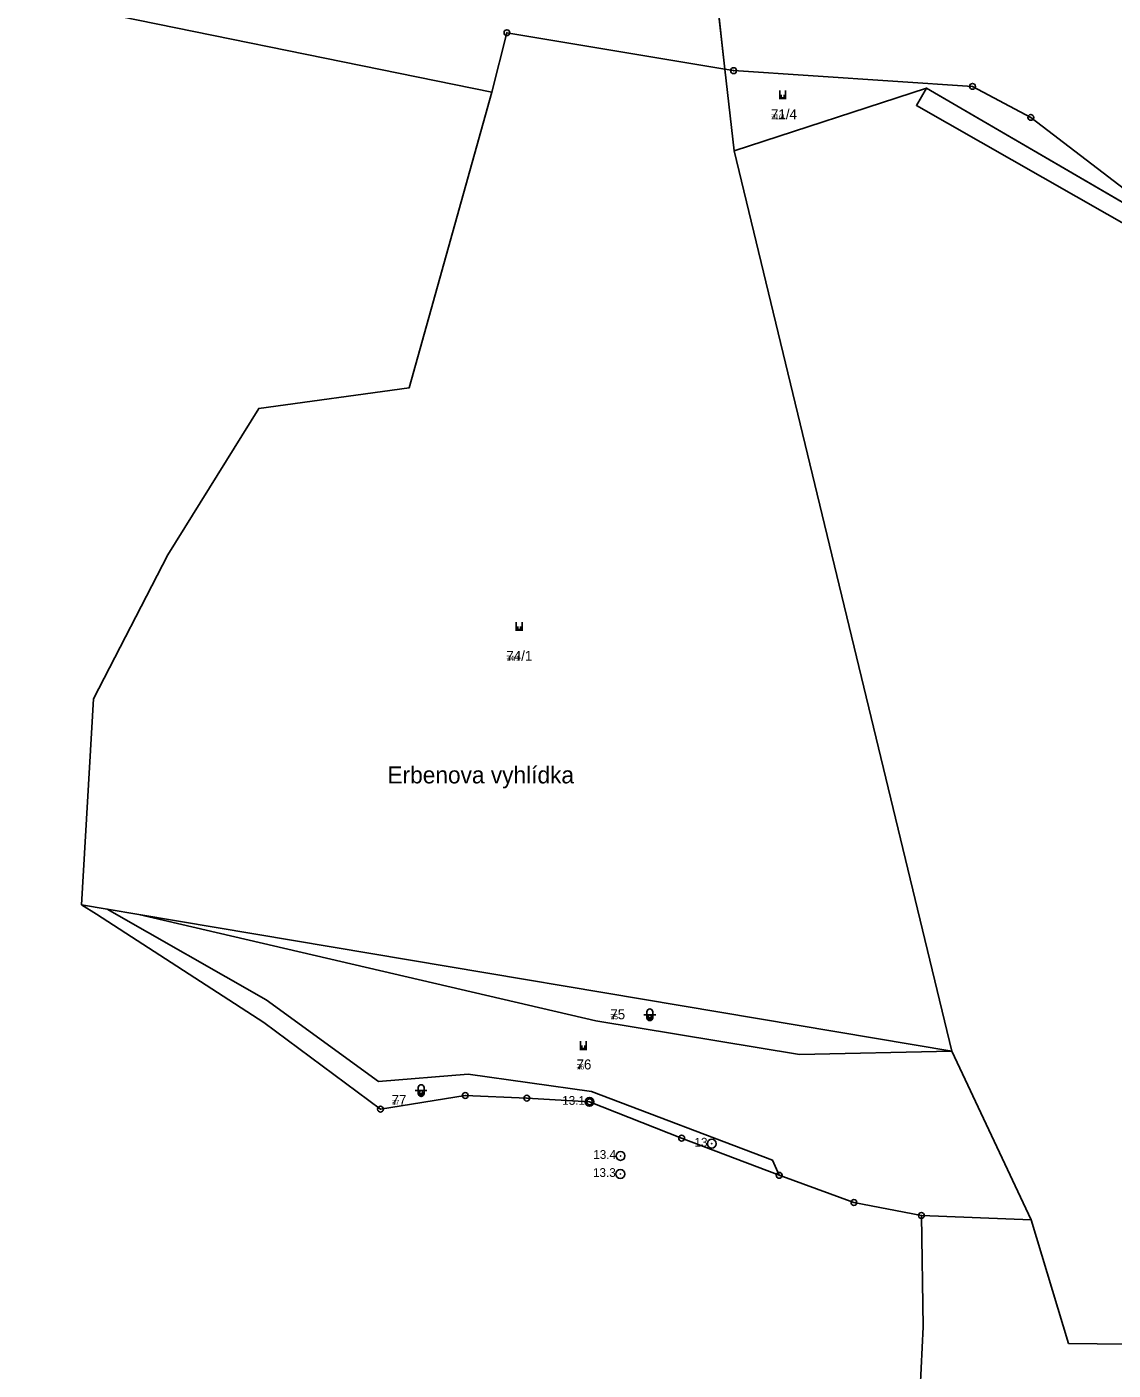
# Model space of a CAD drawing. Extents: x -759873 to -758487, y -975024 to -973516.
# Drawn here: x -759872 to -759686.2, y -974272.1 to -974042.3 of the extents above; entities that cross this region are included whole.
import ezdxf

# ---------------------------------------------------------------- set-up
doc = ezdxf.new("R2010")
doc.units = 0
for name, color, linetype in [('KAT_01_hranice KU', 7, 'Continuous'), ('KAT_02_hranice parcel', 7, 'Continuous'), ('KAT_03_1000_čísla parcelní', 7, 'Continuous'), ('KAT_03_250_čísla parcelní', 7, 'Continuous'), ('KAT_03_500_čísla parcelní', 7, 'Continuous'), ('KAT_05_1000_značky kultur', 7, 'Continuous'), ('KAT_05_250_značky kultur', 7, 'Continuous'), ('KAT_05_500_značky kultur', 7, 'Continuous'), ('KAT_11_značky bodu BP', 7, 'Continuous'), ('KAT_13_popis', 7, 'Continuous'), ('KAT_14_plocha_pozemek', 7, 'Continuous')]:
    doc.layers.add(name, color=color, linetype=linetype)

msp = doc.modelspace()

# ---------------------------------------------------------------- linework, layer by layer
at = {"layer": 'KAT_01_hranice KU'}
msp.add_lwpolyline([(-759872.01, -974037.29), (-759792.52, -974053.5), (-759806.62, -974104.07), (-759832.36, -974107.61), (-759847.91, -974132.63), (-759860.63, -974157.26), (-759862.64, -974192.51), (-759860.12, -974194.14), (-759831.47, -974212.65), (-759811.53, -974227.49), (-759797.03, -974225.14), (-759786.52, -974225.59), (-759775.77, -974226.22), (-759760.03, -974232.43), (-759743.36, -974238.79), (-759730.56, -974243.44), (-759719.03, -974245.68), (-759718.73, -974264.72), (-759719.4, -974278.85)], dxfattribs=at)
at = {"layer": 'KAT_02_hranice parcel'}
for p, q in [((-759762.9, -973958.35), (-759752.64, -974049.58)), ((-759792.52, -974053.5), (-759872.01, -974037.29)), ((-759752.64, -974049.58), (-759751.07, -974063.55)), ((-759751.07, -974063.55), (-759718.13, -974052.81)), ((-759718.13, -974052.81), (-759669.1, -974081.39)), ((-759713.82, -974217.53), (-759751.07, -974063.55)), ((-759862.64, -974192.51), (-759858.3, -974193.24)), ((-759860.12, -974194.14), (-759862.64, -974192.51)), ((-759831.47, -974212.65), (-759860.12, -974194.14)), ((-759858.3, -974193.24), (-759852.88, -974194.15)), ((-759852.88, -974194.15), (-759713.82, -974217.53)), ((-759700.24, -974246.4), (-759713.82, -974217.53)), ((-759760.03, -974232.43), (-759775.77, -974226.22)), ((-759743.36, -974238.79), (-759760.03, -974232.43)), ((-759719.03, -974245.68), (-759700.24, -974246.4)), ((-759718.73, -974264.72), (-759719.03, -974245.68))]:
    msp.add_line(p, q, dxfattribs=at)
for points in [[(-759752.64, -974049.58), (-759789.91, -974043.34), (-759792.52, -974053.5)], [(-759682.38, -974071.6), (-759700.32, -974057.83), (-759710.29, -974052.52), (-759751.14, -974049.83), (-759752.64, -974049.58)], [(-759862.64, -974192.51), (-759860.63, -974157.26), (-759847.91, -974132.63), (-759832.36, -974107.61), (-759806.62, -974104.07), (-759792.52, -974053.5)], [(-759718.13, -974052.81), (-759719.88, -974055.79), (-759670.93, -974083.68), (-759632.05, -974101.17)], [(-759858.3, -974193.24), (-759831.1, -974208.76), (-759811.85, -974222.75), (-759796.53, -974221.51), (-759775.47, -974224.47), (-759744.49, -974236.22), (-759743.36, -974238.79)], [(-759852.88, -974194.15), (-759774.68, -974212.38), (-759739.85, -974218.14), (-759713.82, -974217.53)], [(-759797.03, -974225.14), (-759811.53, -974227.49), (-759831.47, -974212.65)], [(-759775.77, -974226.22), (-759786.52, -974225.59), (-759797.03, -974225.14)], [(-759719.03, -974245.68), (-759730.56, -974243.44), (-759743.36, -974238.79)], [(-759646.41, -974344.61), (-759674.19, -974267.79), (-759693.85, -974267.55), (-759700.24, -974246.4)], [(-759718.64, -974299.18), (-759719.4, -974278.85), (-759718.73, -974264.72)]]:
    msp.add_lwpolyline(points, dxfattribs=at)
at = {"layer": 'KAT_05_1000_značky kultur'}
for p, q in [((-759743.25, -974054.73), (-759743.25, -974053.23)), ((-759742.25, -974054.73), (-759742.25, -974053.23)), ((-759788.32, -974145.67), (-759788.32, -974144.17)), ((-759787.32, -974145.67), (-759787.32, -974144.17)), ((-759766.47, -974211.33), (-759764.47, -974211.33)), ((-759765.97, -974210.83), (-759765.97, -974211.83)), ((-759764.97, -974211.83), (-759764.97, -974210.83)), ((-759777.34, -974217.36), (-759777.34, -974215.86)), ((-759776.34, -974217.36), (-759776.34, -974215.86)), ((-759805.59, -974224.29), (-759803.59, -974224.29)), ((-759805.09, -974223.79), (-759805.09, -974224.79)), ((-759804.09, -974224.79), (-759804.09, -974223.79))]:
    msp.add_line(p, q, dxfattribs=at)
for centre, start, end in [((-759765.47, -974210.83), 0, 180), ((-759765.47, -974211.83), 180, 359.9879), ((-759804.59, -974223.79), 0, 180), ((-759804.59, -974224.79), 180, 359.9879)]:
    msp.add_arc(centre, 0.5, start, end, dxfattribs=at)
at = {"layer": 'KAT_05_250_značky kultur'}
for p, q in [((-759742.87, -974054.73), (-759742.87, -974054.35)), ((-759742.62, -974054.73), (-759742.62, -974054.35)), ((-759787.94, -974145.67), (-759787.94, -974145.3)), ((-759787.69, -974145.67), (-759787.69, -974145.3)), ((-759765.72, -974212.08), (-759765.22, -974212.08)), ((-759765.6, -974211.96), (-759765.6, -974212.21)), ((-759765.34, -974212.21), (-759765.34, -974211.96)), ((-759776.96, -974217.36), (-759776.96, -974216.98)), ((-759776.71, -974217.36), (-759776.71, -974216.98)), ((-759804.84, -974225.04), (-759804.34, -974225.04)), ((-759804.72, -974224.92), (-759804.72, -974225.17)), ((-759804.46, -974225.17), (-759804.46, -974224.92))]:
    msp.add_line(p, q, dxfattribs=at)
for centre, start, end in [((-759765.47, -974211.96), 0, 180), ((-759765.47, -974212.21), 180, 359.9879), ((-759804.59, -974224.92), 0, 180), ((-759804.59, -974225.17), 180, 359.9879)]:
    msp.add_arc(centre, 0.125, start, end, dxfattribs=at)
at = {"layer": 'KAT_05_500_značky kultur'}
for p, q in [((-759743, -974054.73), (-759743, -974053.98)), ((-759742.49, -974054.73), (-759742.49, -974053.98)), ((-759788.07, -974145.67), (-759788.07, -974144.92)), ((-759787.57, -974145.67), (-759787.57, -974144.92)), ((-759765.97, -974211.83), (-759764.97, -974211.83)), ((-759765.72, -974211.58), (-759765.72, -974212.08)), ((-759765.22, -974212.08), (-759765.22, -974211.58)), ((-759777.09, -974217.36), (-759777.09, -974216.61)), ((-759776.58, -974217.36), (-759776.58, -974216.61)), ((-759804.84, -974224.54), (-759804.84, -974225.04)), ((-759804.34, -974225.04), (-759804.34, -974224.54)), ((-759805.09, -974224.79), (-759804.09, -974224.79))]:
    msp.add_line(p, q, dxfattribs=at)
for centre, start, end in [((-759765.47, -974211.58), 0, 180), ((-759765.47, -974212.08), 180, 359.9879), ((-759804.59, -974224.54), 0, 180), ((-759804.59, -974225.04), 180, 359.9879)]:
    msp.add_arc(centre, 0.25, start, end, dxfattribs=at)
at = {"layer": 'KAT_11_značky bodu BP'}
for centre, radius in [((-759789.91, -974043.34), 0.5), ((-759789.91, -974043.34), 0.0303), ((-759751.14, -974049.83), 0.5), ((-759751.14, -974049.83), 0.0303), ((-759710.29, -974052.52), 0.5), ((-759710.29, -974052.52), 0.0303), ((-759700.32, -974057.83), 0.5), ((-759700.32, -974057.83), 0.0303), ((-759797.03, -974225.14), 0.5), ((-759797.03, -974225.14), 0.0303), ((-759786.52, -974225.59), 0.5), ((-759786.52, -974225.59), 0.0303), ((-759775.79, -974226.23), 0.75), ((-759775.77, -974226.22), 0.5), ((-759775.79, -974226.23), 0.03), ((-759775.77, -974226.22), 0.0303), ((-759811.53, -974227.49), 0.5), ((-759811.53, -974227.49), 0.0303), ((-759760.03, -974232.43), 0.5), ((-759760.03, -974232.43), 0.0303), ((-759754.88, -974233.38), 0.75), ((-759754.88, -974233.38), 0.03), ((-759770.47, -974235.48), 0.75), ((-759770.47, -974235.48), 0.03), ((-759770.52, -974238.57), 0.75), ((-759743.36, -974238.79), 0.5), ((-759770.52, -974238.57), 0.03), ((-759743.36, -974238.79), 0.0303), ((-759730.56, -974243.44), 0.5), ((-759730.56, -974243.44), 0.0303), ((-759719.03, -974245.68), 0.5), ((-759719.03, -974245.68), 0.0303)]:
    msp.add_circle(centre, radius, dxfattribs=at)
at = {"layer": 'KAT_14_plocha_pozemek'}
for points in [[(-759792.52, -974053.5), (-759789.91, -974043.34), (-759752.64, -974049.58), (-759762.9, -973958.35), (-759774.3, -973975.7), (-759798.85, -973996.05), (-759828.85, -974009.1), (-759866.03, -974017.98), (-759872.01, -974037.29)], [(-759751.07, -974063.55), (-759752.64, -974049.58), (-759789.91, -974043.34), (-759792.52, -974053.5), (-759806.62, -974104.07), (-759832.36, -974107.61), (-759847.91, -974132.63), (-759860.63, -974157.26), (-759862.64, -974192.51), (-759858.3, -974193.24), (-759852.88, -974194.15), (-759713.82, -974217.53)], [(-759751.07, -974063.55), (-759718.13, -974052.81), (-759669.1, -974081.39), (-759682.38, -974071.6), (-759700.32, -974057.83), (-759710.29, -974052.52), (-759751.14, -974049.83), (-759752.64, -974049.58)], [(-759719.88, -974055.79), (-759670.93, -974083.68), (-759632.05, -974101.17), (-759628.88, -974102.32), (-759621.09, -974101.11), (-759595.87, -974097.2), (-759585.13, -974095.53), (-759586.56, -974092.63), (-759598.89, -974094.51), (-759627.94, -974098.94), (-759669.1, -974081.39), (-759718.13, -974052.81)], [(-759831.47, -974212.65), (-759811.53, -974227.49), (-759797.03, -974225.14), (-759786.52, -974225.59), (-759775.77, -974226.22), (-759760.03, -974232.43), (-759743.36, -974238.79), (-759744.49, -974236.22), (-759775.47, -974224.47), (-759796.53, -974221.51), (-759811.85, -974222.75), (-759831.1, -974208.76), (-759858.3, -974193.24), (-759862.64, -974192.51), (-759860.12, -974194.14)], [(-759713.82, -974217.53), (-759739.85, -974218.14), (-759774.68, -974212.38), (-759852.88, -974194.15), (-759858.3, -974193.24), (-759831.1, -974208.76), (-759811.85, -974222.75), (-759796.53, -974221.51), (-759775.47, -974224.47), (-759744.49, -974236.22), (-759743.36, -974238.79), (-759730.56, -974243.44), (-759719.03, -974245.68), (-759700.24, -974246.4)], [(-759739.85, -974218.14), (-759713.82, -974217.53), (-759852.88, -974194.15), (-759774.68, -974212.38)], [(-759661.16, -974344.3), (-759650.27, -974349.95), (-759644.02, -974351.23), (-759646.41, -974344.61), (-759674.19, -974267.79), (-759693.85, -974267.55), (-759700.24, -974246.4), (-759719.03, -974245.68), (-759718.73, -974264.72), (-759719.4, -974278.85), (-759718.64, -974299.18), (-759717.91, -974329), (-759698.03, -974336.1), (-759681.61, -974340.95), (-759677.07, -974340.17)]]:
    msp.add_lwpolyline(points, close=True, dxfattribs=at)
for points in [[(-759762.9, -973958.35), (-759752.64, -974049.58), (-759751.14, -974049.83), (-759710.29, -974052.52), (-759700.32, -974057.83), (-759682.38, -974071.6), (-759610.17, -974058.97), (-759598.71, -974066.87), (-759592.59, -974066.4), (-759595.2, -974059.1), (-759593.11, -974016.5)], [(-759670.93, -974083.68), (-759719.88, -974055.79), (-759718.13, -974052.81), (-759751.07, -974063.55), (-759713.82, -974217.53), (-759700.24, -974246.4), (-759693.85, -974267.55), (-759674.19, -974267.79)]]:
    msp.add_lwpolyline(points, dxfattribs=at)

# ---------------------------------------------------------------- texts
at = {"layer": 'KAT_03_1000_čísla parcelní'}
for s, p in [('71/4', (-759744.74, -974058.14)), ('74/1', (-759790, -974150.78)), ('75', (-759772.22, -974212.1)), ('76', (-759778, -974220.68)), ('77', (-759809.62, -974226.73))]:
    msp.add_text(s, height=1.7, dxfattribs=at).set_placement(p)
at = {"layer": 'KAT_03_250_čísla parcelní'}
for s, p in [('71/4', (-759744.74, -974058.14)), ('74/1', (-759790, -974150.78)), ('75', (-759772.22, -974212.1)), ('76', (-759778, -974220.68)), ('77', (-759809.62, -974226.73))]:
    msp.add_text(s, height=0.425, dxfattribs=at).set_placement(p)
at = {"layer": 'KAT_03_500_čísla parcelní'}
for s, p in [('71/4', (-759744.74, -974058.14)), ('74/1', (-759790, -974150.78)), ('75', (-759772.22, -974212.1)), ('76', (-759778, -974220.68)), ('77', (-759809.62, -974226.73))]:
    msp.add_text(s, height=0.85, dxfattribs=at).set_placement(p)
at = {"layer": 'KAT_11_značky bodu BP'}
for s, p in [('13.1', (-759780.46, -974226.73)), ('13', (-759757.84, -974233.88)), ('13.4', (-759775.15, -974235.98)), ('13.3', (-759775.2, -974239.07))]:
    msp.add_text(s, height=1.5, dxfattribs=at).set_placement(p)
at = {"layer": 'KAT_13_popis'}
msp.add_text('Erbenova vyhlídka', height=2.9, dxfattribs=at).set_placement((-759810.34, -974171.75))

doc.saveas('drawing.dxf')
